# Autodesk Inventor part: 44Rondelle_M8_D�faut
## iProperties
Created: 2011-01
Part Number: 44Rondelle_M8_D�faut
Document SubType Name: Modeling
Designer: eric
Density: 1 g/cm^3
Mass: 0.218466 g
Surface Area: 4.06271 cm^2
Volume: 0.218466 cm^3
Author: eric
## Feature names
1. Base1
